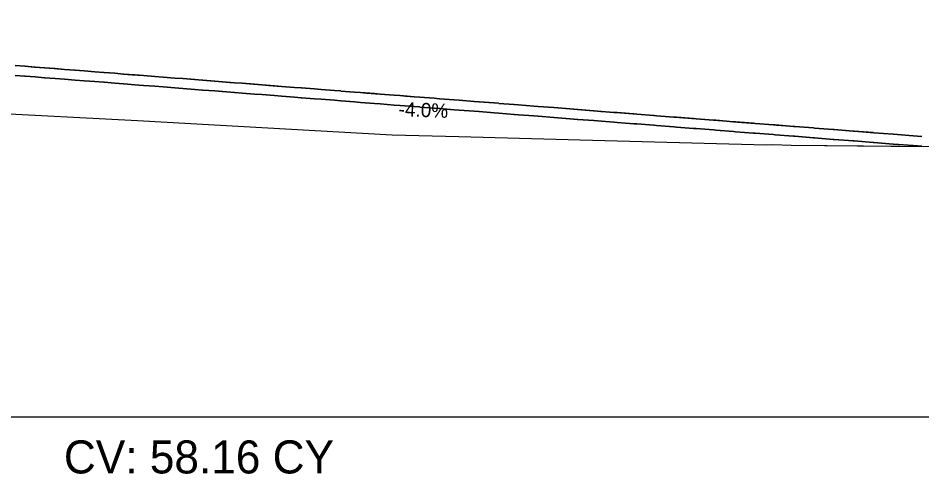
# Model space of a CAD drawing. Extents: x -26 to 4403, y -13 to 9578.
# Drawn here: x 309.83 to 355.79, y 1497.1 to 1520.28 of the extents above; entities that cross this region are included whole.
import ezdxf

# ---------------------------------------------------------------- set-up
doc = ezdxf.new("R2010")
doc.units = 0
for name, color, linetype in [('CONST_LV3', 7, 'Continuous'), ('DTM_P_FINISHED_GRADE', 7, 'Continuous'), ('DTM_X_GROUND', 7, 'Continuous'), ('XS_CELL', 7, 'Continuous'), ('XS_M_SHAPES_EARTHWORK', 7, 'Continuous'), ('XS_P_DR_GRAVEL', 7, 'Continuous'), ('XS_P_TX_FS_BS', 7, 'Continuous'), ('XS_SHEET_EW_TX_VOLUME', 7, 'Continuous')]:
    doc.layers.add(name, color=color, linetype=linetype)

msp = doc.modelspace()

# ---------------------------------------------------------------- linework, layer by layer
at = {"layer": 'CONST_LV3'}
msp.add_lwpolyline([(309.676, 1517.867), (310.176, 1517.828), (310.669, 1517.789), (311.18, 1517.749), (311.662, 1517.711), (312.183, 1517.671), (312.716, 1517.629), (313.187, 1517.592), (313.648, 1517.556), (314.191, 1517.514), (314.746, 1517.47), (315.195, 1517.435), (315.634, 1517.401), (316.199, 1517.357), (316.627, 1517.323), (317.202, 1517.278), (317.62, 1517.245), (318.206, 1517.2), (318.806, 1517.153), (319.21, 1517.121), (319.821, 1517.073), (320.214, 1517.043), (320.599, 1517.012), (321.218, 1516.964), (321.592, 1516.935), (322.222, 1516.886), (322.585, 1516.857), (323.225, 1516.807), (323.578, 1516.779), (324.229, 1516.729), (324.895, 1516.676), (325.233, 1516.65), (325.564, 1516.624), (326.237, 1516.572), (326.557, 1516.547), (327.241, 1516.493), (327.549, 1516.469), (328.244, 1516.415), (328.955, 1516.359), (329.248, 1516.336), (329.535, 1516.314), (330.252, 1516.258), (330.985, 1516.2), (331.256, 1516.179), (331.521, 1516.158), (332.26, 1516.101), (332.514, 1516.081), (333.264, 1516.022), (333.507, 1516.003), (334.267, 1515.944), (335.044, 1515.883), (335.271, 1515.865), (335.493, 1515.848), (336.275, 1515.787), (337.074, 1515.724), (337.279, 1515.708), (337.479, 1515.692), (338.283, 1515.63), (338.472, 1515.615), (339.286, 1515.551), (339.465, 1515.537), (340.29, 1515.473), (340.458, 1515.459), (341.294, 1515.394), (342.149, 1515.327), (342.298, 1515.316), (342.444, 1515.304), (343.302, 1515.237), (343.437, 1515.226), (344.305, 1515.159), (345.194, 1515.089), (345.309, 1515.08), (345.423, 1515.071), (346.313, 1515.002), (346.416, 1514.994), (347.317, 1514.923), (348.238, 1514.851), (348.321, 1514.845), (348.402, 1514.838), (349.325, 1514.766), (350.268, 1514.692), (350.329, 1514.688), (350.388, 1514.683), (351.332, 1514.609), (351.381, 1514.605), (352.336, 1514.531), (352.374, 1514.528), (353.34, 1514.452), (354.328, 1514.375), (354.344, 1514.374), (354.359, 1514.372), (355.348, 1514.295), (355.352, 1514.295), (355.79, 1514.26)], dxfattribs=at)
at = {"layer": 'DTM_P_FINISHED_GRADE'}
msp.add_lwpolyline([(309.679, 1517.866), (310.176, 1517.828), (310.183, 1517.827), (310.694, 1517.787), (311.18, 1517.749), (311.187, 1517.748), (311.709, 1517.708), (312.183, 1517.671), (312.191, 1517.67), (312.723, 1517.628), (313.187, 1517.592), (313.194, 1517.591), (313.738, 1517.549), (314.191, 1517.514), (314.198, 1517.513), (314.753, 1517.47), (315.195, 1517.435), (315.202, 1517.434), (315.768, 1517.39), (316.199, 1517.357), (316.205, 1517.356), (316.782, 1517.311), (317.202, 1517.278), (317.209, 1517.278), (317.797, 1517.232), (318.206, 1517.2), (318.213, 1517.199), (318.812, 1517.152), (319.21, 1517.121), (319.216, 1517.121), (319.827, 1517.073), (320.214, 1517.043), (320.22, 1517.042), (320.841, 1516.993), (321.218, 1516.964), (321.224, 1516.964), (321.856, 1516.914), (322.222, 1516.886), (322.227, 1516.885), (322.871, 1516.835), (323.225, 1516.807), (323.231, 1516.807), (323.885, 1516.755), (324.229, 1516.729), (324.234, 1516.728), (324.9, 1516.676), (325.233, 1516.65), (325.238, 1516.65), (325.915, 1516.597), (326.237, 1516.572), (326.242, 1516.571), (326.93, 1516.517), (327.241, 1516.493), (327.245, 1516.493), (327.945, 1516.438), (328.244, 1516.415), (328.249, 1516.414), (328.959, 1516.359), (329.248, 1516.336), (329.253, 1516.336), (329.974, 1516.279), (330.252, 1516.258), (330.256, 1516.257), (330.989, 1516.2), (331.256, 1516.179), (331.26, 1516.179), (332.004, 1516.121), (332.26, 1516.101), (332.264, 1516.1), (333.018, 1516.041), (333.264, 1516.022), (333.267, 1516.022), (334.033, 1515.962), (334.267, 1515.944), (334.271, 1515.943), (335.048, 1515.882), (335.271, 1515.865), (335.275, 1515.865), (336.063, 1515.803), (336.275, 1515.787), (336.278, 1515.786), (337.077, 1515.724), (337.279, 1515.708), (337.282, 1515.708), (338.092, 1515.644), (338.283, 1515.63), (338.286, 1515.629), (339.107, 1515.565), (339.286, 1515.551), (339.289, 1515.551), (340.122, 1515.486), (340.29, 1515.473), (340.293, 1515.472), (341.136, 1515.406), (341.294, 1515.394), (341.297, 1515.394), (342.151, 1515.327), (342.298, 1515.316), (342.3, 1515.315), (343.166, 1515.248), (343.302, 1515.237), (343.304, 1515.237), (344.18, 1515.168), (344.305, 1515.159), (344.307, 1515.158), (345.195, 1515.089), (345.309, 1515.08), (345.311, 1515.08), (346.21, 1515.01), (346.313, 1515.002), (346.315, 1515.001), (347.225, 1514.93), (347.317, 1514.923), (347.318, 1514.923), (348.24, 1514.851), (348.321, 1514.845), (348.322, 1514.844), (349.254, 1514.772), (349.325, 1514.766), (349.326, 1514.766), (350.269, 1514.692), (350.329, 1514.688), (350.329, 1514.687), (351.284, 1514.613), (351.332, 1514.609), (351.333, 1514.609), (352.299, 1514.533), (352.336, 1514.531), (352.337, 1514.53), (353.313, 1514.454), (353.34, 1514.452), (353.34, 1514.452), (354.328, 1514.375), (354.344, 1514.374), (354.344, 1514.374), (355.343, 1514.295), (355.348, 1514.295), (355.348, 1514.295), (355.79, 1514.26)], dxfattribs=at)
at = {"layer": 'DTM_X_GROUND'}
msp.add_lwpolyline([(262.308, 1520.28), (267.608, 1519.607), (269.532, 1519.51), (276.336, 1518.635), (277.085, 1518.481), (289.466, 1516.992), (290.351, 1516.958), (298.112, 1516.358), (306.607, 1515.6), (308.072, 1515.483), (315.908, 1515.07), (328.844, 1514.348), (332.234, 1514.262), (338.414, 1514.095), (347.871, 1513.84), (348.208, 1513.842), (349.143, 1513.812), (376.688, 1513.569), (384.125, 1513.444), (384.178, 1513.434), (400, 1513.374)], dxfattribs=at)
at = {"layer": 'XS_CELL'}
msp.add_line((250, 1500), (400, 1500), dxfattribs=at)
at = {"layer": 'XS_M_SHAPES_EARTHWORK'}
for points in [[(355.79, 1513.76), (355.348, 1513.795), (355.343, 1513.795), (354.344, 1513.874), (354.328, 1513.875), (353.34, 1513.952), (353.313, 1513.954), (352.336, 1514.031), (352.299, 1514.033), (351.332, 1514.109), (351.284, 1514.113), (350.329, 1514.188), (350.269, 1514.192), (349.326, 1514.266), (349.325, 1514.266), (349.254, 1514.272), (348.322, 1514.344), (348.321, 1514.345), (348.24, 1514.351), (347.318, 1514.423), (347.317, 1514.423), (347.225, 1514.43), (346.315, 1514.501), (346.313, 1514.502), (346.21, 1514.51), (345.311, 1514.58), (345.309, 1514.58), (345.195, 1514.589), (344.307, 1514.658), (344.305, 1514.659), (344.18, 1514.668), (343.304, 1514.737), (343.302, 1514.737), (343.166, 1514.748), (342.3, 1514.815), (342.298, 1514.816), (342.151, 1514.827), (341.297, 1514.894), (341.294, 1514.894), (341.136, 1514.906), (340.293, 1514.972), (340.29, 1514.973), (340.122, 1514.986), (339.289, 1515.051), (339.286, 1515.051), (339.107, 1515.065), (338.286, 1515.129), (338.283, 1515.13), (338.092, 1515.144), (337.282, 1515.208), (337.279, 1515.208), (337.077, 1515.224), (336.278, 1515.286), (336.275, 1515.287), (336.063, 1515.303), (335.275, 1515.365), (335.271, 1515.365), (335.048, 1515.382), (334.271, 1515.443), (334.267, 1515.444), (334.033, 1515.462), (333.267, 1515.522), (333.264, 1515.522), (333.018, 1515.541), (332.264, 1515.6), (332.26, 1515.601), (332.004, 1515.621), (331.26, 1515.679), (331.256, 1515.679), (330.989, 1515.7), (330.256, 1515.757), (330.252, 1515.758), (329.974, 1515.779), (329.253, 1515.836), (329.248, 1515.836), (328.959, 1515.859), (328.249, 1515.914), (328.244, 1515.915), (327.945, 1515.938), (327.245, 1515.993), (327.241, 1515.993), (326.93, 1516.017), (326.242, 1516.071), (326.237, 1516.072), (325.915, 1516.097), (325.238, 1516.15), (325.233, 1516.15), (324.9, 1516.176), (324.234, 1516.228), (324.229, 1516.229), (323.885, 1516.255), (323.231, 1516.307), (323.225, 1516.307), (322.871, 1516.335), (322.227, 1516.385), (322.222, 1516.386), (321.856, 1516.414), (321.224, 1516.464), (321.218, 1516.464), (320.841, 1516.493), (320.22, 1516.542), (320.214, 1516.543), (319.827, 1516.573), (319.216, 1516.621), (319.21, 1516.621), (318.812, 1516.652), (318.213, 1516.699), (318.206, 1516.7), (317.797, 1516.732), (317.209, 1516.778), (317.202, 1516.778), (316.782, 1516.811), (316.205, 1516.856), (316.199, 1516.857), (315.768, 1516.89), (315.202, 1516.934), (315.195, 1516.935), (314.753, 1516.97), (314.198, 1517.013), (314.191, 1517.014), (313.738, 1517.049), (313.194, 1517.091), (313.187, 1517.092), (312.723, 1517.128), (312.191, 1517.17), (312.183, 1517.171), (311.709, 1517.208), (311.187, 1517.248), (311.18, 1517.249), (310.694, 1517.287), (310.183, 1517.327), (310.176, 1517.328), (309.679, 1517.366)], [(308.072, 1515.483), (315.908, 1515.07), (328.844, 1514.348), (332.234, 1514.262), (338.414, 1514.095), (347.871, 1513.84), (348.208, 1513.842), (349.143, 1513.812), (355.887, 1513.753)]]:
    msp.add_lwpolyline(points, dxfattribs=at)
at = {"layer": 'XS_P_DR_GRAVEL'}
for points in [[(355.79, 1514.26), (355.348, 1514.295), (355.348, 1514.295), (355.343, 1514.295), (354.344, 1514.374), (354.344, 1514.374), (354.328, 1514.375), (353.34, 1514.452), (353.34, 1514.452), (353.313, 1514.454), (352.337, 1514.53), (352.336, 1514.531), (352.299, 1514.533), (351.333, 1514.609), (351.332, 1514.609), (351.284, 1514.613), (350.329, 1514.687), (350.329, 1514.688), (350.269, 1514.692), (349.326, 1514.766), (349.325, 1514.766), (349.254, 1514.772), (348.322, 1514.844), (348.321, 1514.845), (348.24, 1514.851), (347.318, 1514.923), (347.317, 1514.923), (347.225, 1514.93), (346.315, 1515.001), (346.313, 1515.002), (346.21, 1515.01), (345.311, 1515.08), (345.309, 1515.08), (345.195, 1515.089), (344.307, 1515.158), (344.305, 1515.159), (344.18, 1515.168), (343.304, 1515.237), (343.302, 1515.237), (343.166, 1515.248), (342.3, 1515.315), (342.298, 1515.316), (342.151, 1515.327), (341.297, 1515.394), (341.294, 1515.394), (341.136, 1515.406), (340.293, 1515.472), (340.29, 1515.473), (340.122, 1515.486), (339.289, 1515.551), (339.286, 1515.551), (339.107, 1515.565), (338.286, 1515.629), (338.283, 1515.63), (338.092, 1515.644), (337.282, 1515.708), (337.279, 1515.708), (337.077, 1515.724), (336.278, 1515.786), (336.275, 1515.787), (336.063, 1515.803), (335.275, 1515.865), (335.271, 1515.865), (335.048, 1515.882), (334.271, 1515.943), (334.267, 1515.944), (334.033, 1515.962), (333.267, 1516.022), (333.264, 1516.022), (333.018, 1516.041), (332.264, 1516.1), (332.26, 1516.101), (332.004, 1516.121), (331.26, 1516.179), (331.256, 1516.179), (330.989, 1516.2), (330.256, 1516.257), (330.252, 1516.258), (329.974, 1516.279), (329.253, 1516.336), (329.248, 1516.336), (328.959, 1516.359), (328.249, 1516.414), (328.244, 1516.415), (327.945, 1516.438), (327.245, 1516.493), (327.241, 1516.493), (326.93, 1516.517), (326.242, 1516.571), (326.237, 1516.572), (325.915, 1516.597), (325.238, 1516.65), (325.233, 1516.65), (324.9, 1516.676), (324.234, 1516.728), (324.229, 1516.729), (323.885, 1516.755), (323.231, 1516.807), (323.225, 1516.807), (322.871, 1516.835), (322.227, 1516.885), (322.222, 1516.886), (321.856, 1516.914), (321.224, 1516.964), (321.218, 1516.964), (320.841, 1516.993), (320.22, 1517.042), (320.214, 1517.043), (319.827, 1517.073), (319.216, 1517.121), (319.21, 1517.121), (318.812, 1517.152), (318.213, 1517.199), (318.206, 1517.2), (317.797, 1517.232), (317.209, 1517.278), (317.202, 1517.278), (316.782, 1517.311), (316.205, 1517.356), (316.199, 1517.357), (315.768, 1517.39), (315.202, 1517.434), (315.195, 1517.435), (314.753, 1517.47), (314.198, 1517.513), (314.191, 1517.514), (313.738, 1517.549), (313.194, 1517.591), (313.187, 1517.592), (312.723, 1517.628), (312.191, 1517.67), (312.183, 1517.671), (311.709, 1517.708), (311.187, 1517.748), (311.18, 1517.749), (310.694, 1517.787), (310.183, 1517.827), (310.176, 1517.828), (309.679, 1517.866)], [(309.679, 1517.366), (310.176, 1517.328), (310.183, 1517.327), (310.694, 1517.287), (311.18, 1517.249), (311.187, 1517.248), (311.709, 1517.208), (312.183, 1517.171), (312.191, 1517.17), (312.723, 1517.128), (313.187, 1517.092), (313.194, 1517.091), (313.738, 1517.049), (314.191, 1517.014), (314.198, 1517.013), (314.753, 1516.97), (315.195, 1516.935), (315.202, 1516.934), (315.768, 1516.89), (316.199, 1516.857), (316.205, 1516.856), (316.782, 1516.811), (317.202, 1516.778), (317.209, 1516.778), (317.797, 1516.732), (318.206, 1516.7), (318.213, 1516.699), (318.812, 1516.652), (319.21, 1516.621), (319.216, 1516.621), (319.827, 1516.573), (320.214, 1516.543), (320.22, 1516.542), (320.841, 1516.493), (321.218, 1516.464), (321.224, 1516.464), (321.856, 1516.414), (322.222, 1516.386), (322.227, 1516.385), (322.871, 1516.335), (323.225, 1516.307), (323.231, 1516.307), (323.885, 1516.255), (324.229, 1516.229), (324.234, 1516.228), (324.9, 1516.176), (325.233, 1516.15), (325.238, 1516.15), (325.915, 1516.097), (326.237, 1516.072), (326.242, 1516.071), (326.93, 1516.017), (327.241, 1515.993), (327.245, 1515.993), (327.945, 1515.938), (328.244, 1515.915), (328.249, 1515.914), (328.959, 1515.859), (329.248, 1515.836), (329.253, 1515.836), (329.974, 1515.779), (330.252, 1515.758), (330.256, 1515.757), (330.989, 1515.7), (331.256, 1515.679), (331.26, 1515.679), (332.004, 1515.621), (332.26, 1515.601), (332.264, 1515.6), (333.018, 1515.541), (333.264, 1515.522), (333.267, 1515.522), (334.033, 1515.462), (334.267, 1515.444), (334.271, 1515.443), (335.048, 1515.382), (335.271, 1515.365), (335.275, 1515.365), (336.063, 1515.303), (336.275, 1515.287), (336.278, 1515.286), (337.077, 1515.224), (337.279, 1515.208), (337.282, 1515.208), (338.092, 1515.144), (338.283, 1515.13), (338.286, 1515.129), (339.107, 1515.065), (339.286, 1515.051), (339.289, 1515.051), (340.122, 1514.986), (340.29, 1514.973), (340.293, 1514.972), (341.136, 1514.906), (341.294, 1514.894), (341.297, 1514.894), (342.151, 1514.827), (342.298, 1514.816), (342.3, 1514.815), (343.166, 1514.748), (343.302, 1514.737), (343.304, 1514.737), (344.18, 1514.668), (344.305, 1514.659), (344.307, 1514.658), (345.195, 1514.589), (345.309, 1514.58), (345.311, 1514.58), (346.21, 1514.51), (346.313, 1514.502), (346.315, 1514.501), (347.225, 1514.43), (347.317, 1514.423), (347.318, 1514.423), (348.24, 1514.351), (348.321, 1514.345), (348.322, 1514.344), (349.254, 1514.272), (349.325, 1514.266), (349.326, 1514.266), (350.269, 1514.192), (350.329, 1514.188), (350.329, 1514.187), (351.284, 1514.113), (351.332, 1514.109), (351.333, 1514.109), (352.299, 1514.033), (352.336, 1514.031), (352.337, 1514.03), (353.313, 1513.954), (353.34, 1513.952), (353.34, 1513.952), (354.328, 1513.875), (354.344, 1513.874), (354.344, 1513.874), (355.343, 1513.795), (355.348, 1513.795), (355.348, 1513.795), (355.79, 1513.76)]]:
    msp.add_lwpolyline(points, dxfattribs=at)

# ---------------------------------------------------------------- texts
at = {"layer": 'XS_P_TX_FS_BS'}
msp.add_text('-4.0%', height=0.72, rotation=357.6852, dxfattribs=at).set_placement((329.169, 1515.299))
msp.add_text('-4.0%', height=0.72, rotation=357.6852, dxfattribs=at).set_placement((329.169, 1515.299))
msp.add_text('-4.0%', height=0.72, rotation=357.6852, dxfattribs=at).set_placement((329.169, 1515.299))
at = {"layer": 'XS_SHEET_EW_TX_VOLUME'}
msp.add_text('CV: 58.16 CY', height=1.68, dxfattribs=at).set_placement((312.158, 1497.12))

doc.saveas('drawing.dxf')
